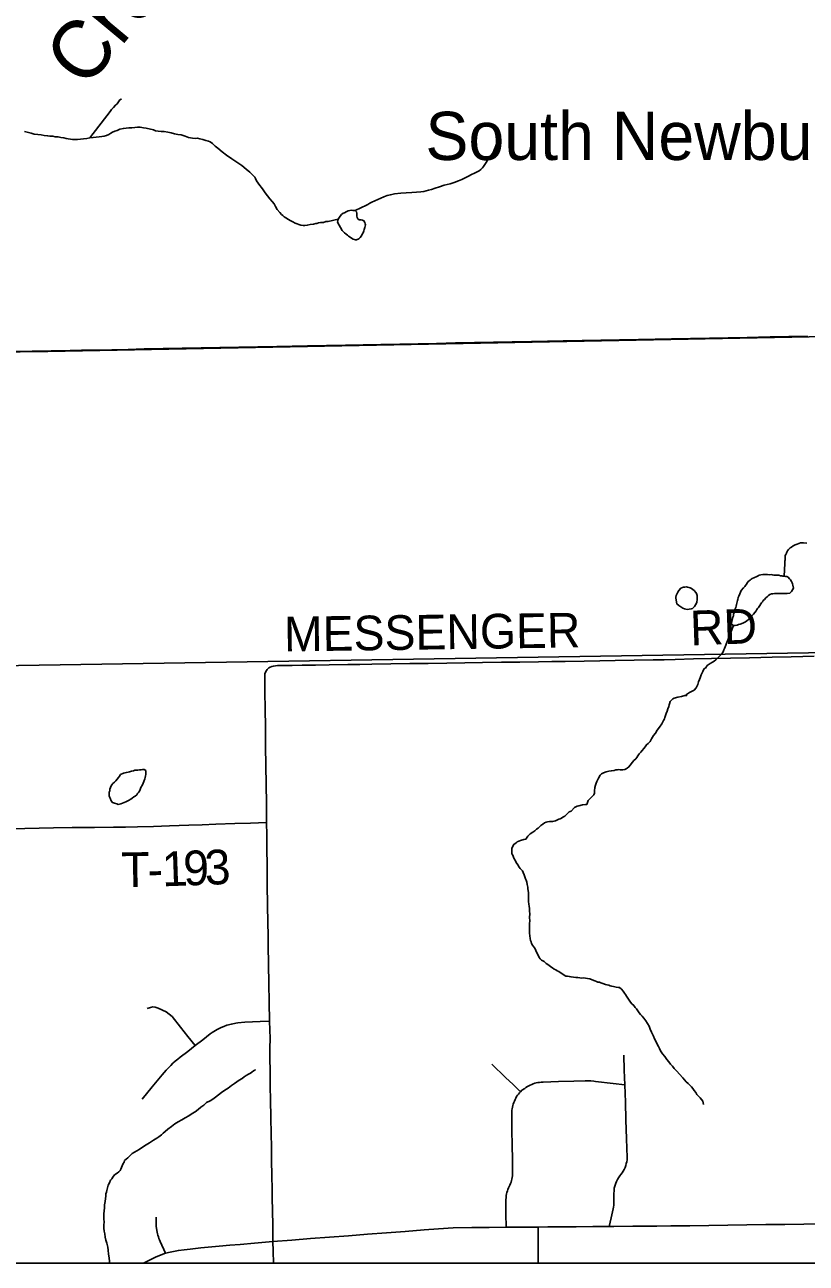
# Model space of a CAD drawing. Extents: x 103424 to 286016, y 38711 to 110967.
# Drawn here: x 136194 to 142995, y 38711 to 49490 of the extents above; entities that cross this region are included whole.
import ezdxf

# ---------------------------------------------------------------- set-up
doc = ezdxf.new("R2010")
doc.units = 0
for name, color, linetype in [('GM_X_Corporation', 7, 'Continuous'), ('GM_X_County_Road', 7, 'Continuous'), ('GM_X_County_Road_Text', 7, 'Continuous'), ('GM_X_Minor_Lake', 7, 'Continuous'), ('GM_X_Minor_River', 7, 'Continuous'), ('GM_X_Minor_River_Text', 7, 'Continuous'), ('GM_X_Rail_Line', 7, 'Continuous'), ('GM_X_Township_Road', 7, 'Continuous'), ('GM_X_Township_Road_Text', 7, 'Continuous'), ('GM_X_Unincorporated_Text', 7, 'Continuous')]:
    doc.layers.add(name, color=color, linetype=linetype)

msp = doc.modelspace()

# ---------------------------------------------------------------- linework, layer by layer
at = {"layer": 'GM_X_Corporation'}
for points in [[(103424, 96535), (103424, 38711), (175680, 38711), (175680, 110967), (119699, 110967), (119717, 106543), (119720, 106323), (119721, 106006), (119710, 99446), (119706, 99064), (119664, 96690), (117026, 96688), (115542, 96665), (105082, 96575)], [(119964, 38711), (149533, 38711), (149528, 39851), (149476, 42605), (149451, 44181), (147524, 44123), (147512, 44122), (144100, 44042), (133605, 43873), (130307, 43800), (126994, 43728), (121865, 43580), (119934, 43543)]]:
    msp.add_lwpolyline(points, close=True, dxfattribs=at)
msp.add_lwpolyline([(149451, 44181), (147524, 44123), (147512, 44122), (144100, 44042), (133605, 43873), (130307, 43800), (126994, 43728), (121865, 43580), (119934, 43543), (119908, 46302), (119860, 51427), (119800, 57497), (119747, 63221), (119711, 67089)], dxfattribs=at)
at = {"layer": 'GM_X_County_Road'}
for points in [[(136094, 46645), (136259, 46648), (136424, 46651), (136589, 46655), (136688, 46657), (136788, 46659), (136953, 46662), (137093, 46665), (137233, 46669), (137398, 46672), (137563, 46675), (137728, 46678), (137893, 46681), (138058, 46684), (138223, 46687), (138388, 46691), (138521, 46693), (138655, 46696), (138820, 46699), (138985, 46702), (139139, 46705), (139294, 46708), (139459, 46711), (139618, 46714), (139777, 46717), (139942, 46721), (140107, 46724), (140272, 46727), (140437, 46730), (140603, 46733), (140742, 46736), (140881, 46738), (141046, 46742), (141208, 46745), (141370, 46748), (141535, 46751), (141679, 46754), (141822, 46756), (141987, 46760), (142152, 46763), (142317, 46766), (142482, 46769), (142581, 46771), (142680, 46773), (142845, 46776), (143010, 46778)], [(138358, 38711), (138355, 38817), (138353, 38901), (138352, 39046), (138350, 39165), (138348, 39283), (138347, 39371), (138345, 39458), (138342, 39623), (138340, 39728), (138339, 39833), (138336, 39981), (138333, 40129), (138331, 40253), (138329, 40376), (138326, 40501), (138328, 40584), (138329, 40668), (138323, 40817), (138320, 40982), (138318, 41147), (138315, 41312), (138312, 41477), (138311, 41573), (138309, 41668), (138307, 41834), (138305, 41999), (138304, 42164), (138302, 42329), (138300, 42438), (138299, 42547), (138297, 42712), (138295, 42877), (138292, 43042), (138290, 43207), (138288, 43373), (138286, 43538), (138284, 43678), (138282, 43819), (138284, 43841), (138292, 43861), (138305, 43878), (138318, 43892), (138330, 43899), (138343, 43904), (138358, 43908), (138376, 43911), (138395, 43912), (138434, 43913), (138521, 43914), (138608, 43915), (138725, 43917), (138842, 43918), (139007, 43921), (139111, 43923), (139215, 43925), (139380, 43928), (139545, 43930), (139706, 43932), (139867, 43935), (140023, 43937), (140178, 43939), (140343, 43941), (140503, 43943), (140664, 43946), (140781, 43947), (140898, 43949), (141063, 43952), (141198, 43954), (141333, 43956), (141498, 43959), (141663, 43962), (141759, 43964), (141855, 43966), (142014, 43970), (142172, 43974), (142336, 43978), (142500, 43981), (142600, 43983), (142700, 43985), (142865, 43990), (142965, 43992), (143065, 43995)]]:
    msp.add_lwpolyline(points, dxfattribs=at)
at = {"layer": 'GM_X_Minor_Lake'}
for points in [[(139050, 47874), (139036, 47875), (139024, 47874), (139010, 47870), (138992, 47862), (138978, 47853), (138966, 47849), (138952, 47838), (138940, 47824), (138932, 47814), (138922, 47799), (138919, 47783), (138915, 47771)], [(138915, 47771), (138957, 47699), (138967, 47689), (138977, 47680), (138992, 47668), (139002, 47658), (139012, 47650), (139025, 47642), (139039, 47632), (139053, 47625), (139072, 47619), (139082, 47619), (139100, 47628), (139112, 47638), (139125, 47653), (139131, 47667), (139139, 47679), (139145, 47697), (139149, 47708), (139154, 47726), (139158, 47738), (139160, 47748), (139158, 47758), (139153, 47770), (139145, 47784), (139133, 47790), (139122, 47792), (139104, 47791), (139092, 47801), (139086, 47813), (139085, 47825), (139085, 47837), (139085, 47849), (139081, 47861), (139070, 47873), (139050, 47874)], [(142827, 44687), (142815, 44688), (142803, 44692), (142792, 44692), (142782, 44694), (142772, 44695), (142756, 44699), (142744, 44699), (142730, 44701), (142713, 44700), (142701, 44702), (142691, 44704), (142675, 44703), (142657, 44705), (142645, 44705), (142630, 44704), (142618, 44704), (142600, 44702), (142586, 44699), (142576, 44695), (142564, 44689), (142540, 44676), (142526, 44670), (142516, 44666), (142506, 44655), (142494, 44647), (142484, 44635), (142475, 44622), (142467, 44610), (142461, 44600), (142449, 44589), (142429, 44565), (142416, 44538), (142408, 44518), (142404, 44506), (142399, 44489), (142397, 44479), (142391, 44455), (142389, 44445), (142386, 44431), (142382, 44418), (142376, 44406), (142370, 44390), (142367, 44374), (142363, 44359), (142361, 44347), (142355, 44335), (142348, 44301), (142345, 44272)], [(142345, 44272), (142348, 44301), (142355, 44335), (142361, 44347), (142363, 44359), (142367, 44374), (142370, 44390), (142376, 44406), (142382, 44418), (142386, 44431), (142389, 44445), (142391, 44455), (142397, 44479), (142399, 44489), (142404, 44506), (142408, 44518), (142416, 44538), (142429, 44565), (142449, 44589), (142461, 44600), (142467, 44610), (142475, 44622), (142484, 44635), (142494, 44647), (142506, 44655), (142516, 44666), (142526, 44670), (142540, 44676), (142564, 44689), (142576, 44695), (142586, 44699), (142600, 44702), (142618, 44704), (142630, 44704), (142645, 44705), (142657, 44705), (142675, 44703), (142691, 44704), (142701, 44702), (142713, 44700), (142730, 44701), (142744, 44699), (142756, 44699), (142772, 44695), (142782, 44694), (142792, 44692), (142803, 44692), (142815, 44688), (142827, 44687), (142837, 44681), (142850, 44669), (142858, 44659), (142868, 44643), (142873, 44633), (142877, 44623), (142879, 44613), (142884, 44587), (142868, 44558), (142852, 44544), (142828, 44539), (142814, 44539), (142802, 44541), (142792, 44540), (142780, 44540), (142769, 44540), (142759, 44540), (142745, 44539), (142733, 44539), (142719, 44539), (142703, 44536), (142693, 44536), (142679, 44532), (142667, 44524), (142657, 44513), (142645, 44501), (142633, 44489), (142621, 44478), (142615, 44468), (142605, 44460), (142600, 44449), (142590, 44435), (142580, 44419), (142570, 44410), (142564, 44400), (142558, 44388), (142549, 44376), (142535, 44361), (142521, 44345), (142507, 44326), (142477, 44303), (142467, 44293), (142443, 44283), (142419, 44272), (142405, 44270), (142393, 44265), (142375, 44261), (142361, 44261), (142345, 44272)], [(142345, 44272), (142361, 44261), (142375, 44261), (142393, 44265), (142405, 44270), (142419, 44272), (142443, 44283), (142467, 44293), (142477, 44303), (142507, 44326), (142521, 44345), (142535, 44361), (142549, 44376), (142558, 44388), (142564, 44400), (142570, 44410), (142580, 44419), (142590, 44435), (142600, 44449), (142605, 44460), (142615, 44468), (142621, 44478), (142633, 44489), (142645, 44501), (142657, 44513), (142667, 44524), (142679, 44532), (142693, 44536), (142703, 44536), (142719, 44539), (142733, 44539), (142745, 44539), (142759, 44540), (142769, 44540), (142780, 44540), (142792, 44540), (142802, 44541), (142814, 44539), (142828, 44539), (142852, 44544), (142868, 44558), (142884, 44587), (142879, 44613), (142877, 44623), (142873, 44633), (142868, 44643), (142858, 44659), (142850, 44669), (142837, 44681), (142827, 44687)], [(142034, 44550), (142019, 44566), (142009, 44576), (141996, 44584), (141984, 44589), (141974, 44593), (141962, 44595), (141952, 44597), (141940, 44595), (141927, 44594), (141917, 44592), (141905, 44586), (141886, 44565), (141878, 44553), (141868, 44534), (141864, 44524), (141861, 44508), (141859, 44502), (141859, 44500)], [(141859, 44500), (141870, 44450), (141886, 44436), (141905, 44424), (141921, 44412), (141936, 44407), (141948, 44403), (141958, 44401), (141994, 44406), (142004, 44410), (142014, 44417), (142022, 44427), (142032, 44441), (142042, 44462), (142045, 44490), (142046, 44512), (142046, 44524), (142040, 44540), (142034, 44550), (142019, 44566), (142009, 44576), (141996, 44584), (141984, 44589), (141974, 44593), (141962, 44595), (141952, 44597), (141940, 44595), (141927, 44594), (141917, 44592), (141905, 44586), (141886, 44565), (141878, 44553), (141868, 44534), (141864, 44524), (141861, 44508), (141859, 44502), (141859, 44500)], [(141859, 44500), (141870, 44450), (141886, 44436), (141905, 44424), (141921, 44412), (141936, 44407), (141948, 44403), (141958, 44401), (141994, 44406), (142004, 44410), (142014, 44417), (142022, 44427), (142032, 44441), (142042, 44462), (142045, 44490), (142046, 44512), (142046, 44524), (142040, 44540), (142034, 44550)], [(137027, 42964), (137019, 42951), (137009, 42939), (136997, 42925), (136986, 42910), (136974, 42898), (136960, 42885), (136952, 42875), (136946, 42865), (136940, 42851), (136935, 42836), (136933, 42824), (136929, 42810), (136929, 42798), (136930, 42780), (136932, 42770), (136936, 42758), (136947, 42736), (136957, 42722), (136974, 42714), (136996, 42708), (137008, 42705), (137030, 42709), (137044, 42716), (137060, 42722), (137074, 42726), (137086, 42733), (137098, 42737), (137118, 42749), (137130, 42760), (137142, 42770), (137156, 42777), (137170, 42789), (137176, 42799), (137184, 42809), (137192, 42820), (137197, 42834), (137205, 42852), (137219, 42875), (137225, 42889), (137230, 42905), (137238, 42926), (137242, 42938), (137245, 42954), (137247, 42964), (137249, 42974), (137249, 42987), (137248, 42999), (137234, 43008), (137220, 43008), (137206, 43006), (137192, 43005), (137178, 43003), (137166, 43003), (137151, 43001), (137139, 42998), (137123, 42994), (137107, 42989), (137093, 42985), (137079, 42983), (137065, 42978), (137053, 42976), (137027, 42964)], [(137156, 42777), (137170, 42789), (137176, 42799), (137184, 42809), (137192, 42820), (137197, 42834), (137205, 42852), (137219, 42875), (137225, 42889), (137230, 42905), (137238, 42926), (137242, 42938), (137245, 42954), (137247, 42964), (137249, 42974), (137249, 42987), (137248, 42999), (137234, 43008), (137220, 43008), (137206, 43006), (137192, 43005), (137178, 43003), (137166, 43003), (137151, 43001), (137139, 42998), (137123, 42994), (137107, 42989), (137093, 42985), (137079, 42983), (137065, 42978), (137053, 42976), (137027, 42964)], [(137027, 42964), (137019, 42951), (137009, 42939), (136997, 42925), (136986, 42910), (136974, 42898), (136960, 42885), (136952, 42875), (136946, 42865), (136940, 42851), (136935, 42836), (136933, 42824), (136929, 42810), (136929, 42798), (136930, 42780), (136932, 42770), (136936, 42758), (136947, 42736), (136957, 42722), (136974, 42714), (136996, 42708), (137008, 42705), (137030, 42709), (137044, 42716), (137060, 42722), (137074, 42726), (137086, 42733), (137098, 42737), (137118, 42749), (137130, 42760), (137142, 42770), (137156, 42777)]]:
    msp.add_lwpolyline(points, dxfattribs=at)
at = {"layer": 'GM_X_Minor_River'}
for points in [[(136759, 48505), (136936, 48735), (136949, 48752), (136965, 48770), (136983, 48789), (136999, 48803), (137009, 48818), (137022, 48836), (137032, 48842), (137034, 48843), (137036, 48845)], [(136192, 48560), (136226, 48552), (136251, 48545), (136277, 48539), (136307, 48536), (136336, 48533), (136364, 48527), (136392, 48524), (136415, 48520), (136437, 48519), (136459, 48515)], [(136459, 48515), (136486, 48514), (136508, 48508), (136534, 48505), (136555, 48501), (136573, 48497), (136593, 48494), (136611, 48490), (136632, 48491), (136654, 48491), (136678, 48494), (136704, 48498), (136735, 48501), (136759, 48505), (136789, 48510), (136815, 48513), (136843, 48515), (136866, 48518), (136884, 48520), (136904, 48527), (136926, 48535), (136942, 48546), (136958, 48556), (136978, 48565), (136998, 48571), (137020, 48580), (137052, 48587), (137076, 48591), (137100, 48592), (137125, 48594), (137151, 48597), (137175, 48599), (137199, 48598), (137226, 48594), (137250, 48591), (137315, 48576), (137333, 48568), (137356, 48563), (137382, 48561), (137408, 48560), (137439, 48555), (137469, 48549), (137498, 48542), (137526, 48536), (137556, 48531), (137589, 48521), (137620, 48508), (137654, 48503), (137676, 48501), (137697, 48502), (137719, 48498), (137743, 48491), (137770, 48483), (137792, 48477), (137808, 48470), (137827, 48456), (137850, 48434), (137874, 48415), (137913, 48383), (137950, 48356), (137995, 48324), (138041, 48295), (138082, 48266), (138121, 48234), (138152, 48207), (138174, 48187), (138189, 48173), (138195, 48163), (138201, 48151), (138210, 48131), (138226, 48111), (138239, 48091), (138253, 48074), (138268, 48052), (138287, 48028), (138308, 48000), (138328, 47974), (138347, 47951), (138364, 47931), (138376, 47909), (138391, 47883), (138414, 47855), (138428, 47839), (138441, 47829), (138453, 47818), (138504, 47786), (138527, 47775), (138547, 47763), (138565, 47757), (138578, 47752), (138596, 47746), (138618, 47742), (138632, 47743), (138653, 47745), (138679, 47752), (138707, 47754), (138727, 47759), (138737, 47761), (138751, 47765), (138769, 47768), (138781, 47770)], [(139070, 47873), (139168, 47920), (139180, 47926), (139196, 47937), (139216, 47947), (139240, 47958), (139266, 47970), (139294, 47981), (139320, 47992), (139348, 48003), (139376, 48011), (139411, 48018), (139467, 48025), (139514, 48028), (139562, 48031), (139604, 48034), (139641, 48037), (139667, 48040), (139687, 48044), (139709, 48051), (139735, 48057), (139767, 48068), (139804, 48079), (139844, 48094), (139896, 48105), (139932, 48118), (139968, 48131), (139998, 48144), (140028, 48159), (140056, 48173), (140082, 48186), (140108, 48199), (140132, 48209), (140150, 48220), (140164, 48230), (140178, 48245), (140186, 48257), (140197, 48273), (140209, 48292), (140221, 48310), (140233, 48329), (140245, 48343), (140254, 48355), (140264, 48370), (140272, 48384), (140280, 48400), (140287, 48423), (140297, 48445), (140306, 48470), (140316, 48494), (140324, 48508), (140332, 48527), (140334, 48529), (140333, 48531)], [(138781, 47770), (138794, 47770), (138814, 47777), (138824, 47777), (138836, 47779), (138922, 47799)], [(142803, 44692), (142811, 44856), (142812, 44830), (142811, 44856), (142813, 44870), (142817, 44880), (142823, 44890), (142826, 44901), (142832, 44911), (142842, 44923), (142856, 44936), (142868, 44944), (142880, 44954), (142898, 44965), (142916, 44969), (142944, 44980), (142970, 44980), (143001, 44979)], [(141277, 42993), (141299, 42998), (141323, 43000), (141339, 43005), (141351, 43005), (141361, 43007), (141375, 43006), (141398, 43006), (141416, 43008), (141428, 43015), (141438, 43021), (141452, 43031), (141495, 43087), (141511, 43101), (141521, 43114), (141530, 43128), (141542, 43144), (141556, 43159), (141568, 43173), (141582, 43190), (141593, 43206), (141605, 43223), (141619, 43235), (141637, 43253), (141648, 43276), (141666, 43303), (141684, 43325), (141699, 43350), (141719, 43376), (141739, 43407), (141752, 43434), (141762, 43450), (141766, 43460), (141771, 43478), (141777, 43495), (141785, 43515), (141792, 43537), (141798, 43556), (141802, 43570), (141804, 43580), (141811, 43600), (141833, 43623), (141845, 43629), (141877, 43638), (141911, 43645), (141940, 43652), (141954, 43652), (141953, 43662), (141979, 43677), (142003, 43689), (142019, 43698), (142037, 43720), (142051, 43747), (142058, 43771), (142066, 43792), (142072, 43806), (142081, 43832), (142095, 43861), (142108, 43886), (142118, 43890), (142134, 43912), (142160, 43931), (142180, 43942), (142194, 43952), (142208, 43964), (142224, 43977), (142261, 44016), (142271, 44032), (142279, 44049), (142285, 44061), (142361, 44261)], [(140639, 41441), (140630, 41457), (140622, 41469), (140614, 41479), (140605, 41495), (140601, 41507), (140595, 41519), (140592, 41537), (140590, 41561), (140587, 41585), (140587, 41609), (140586, 41640), (140587, 41668), (140589, 41692), (140588, 41720), (140590, 41753), (140587, 41775), (140587, 41799), (140584, 41819), (140582, 41837), (140579, 41860), (140579, 41884), (140578, 41908), (140578, 41934), (140575, 41956), (140573, 41970), (140571, 41985), (140566, 42007), (140564, 42029), (140557, 42045), (140553, 42057), (140546, 42073), (140540, 42091), (140533, 42111), (140525, 42125), (140517, 42135), (140506, 42147), (140496, 42159), (140486, 42179), (140471, 42198), (140462, 42218), (140454, 42232), (140448, 42244), (140444, 42254), (140441, 42264), (140433, 42274), (140434, 42325), (140451, 42356), (140471, 42370), (140479, 42380), (140509, 42391), (140537, 42400), (140556, 42402), (140571, 42429), (140593, 42447), (140617, 42462), (140633, 42475), (140647, 42489), (140661, 42499), (140675, 42510), (140686, 42522), (140702, 42533), (140718, 42545), (140732, 42549), (140742, 42552), (140762, 42556), (140775, 42556), (140791, 42557), (140801, 42559), (140813, 42561), (140825, 42568), (140841, 42576), (140855, 42580), (140865, 42585), (140877, 42593), (140895, 42603), (140913, 42620), (140932, 42639), (140949, 42645), (140978, 42678), (141002, 42689), (141016, 42691), (141048, 42702), (141073, 42704), (141085, 42704), (141098, 42737), (141126, 42768), (141148, 42787), (141153, 42801), (141153, 42823), (141156, 42851), (141162, 42872), (141166, 42888), (141173, 42904), (141179, 42914), (141187, 42933), (141203, 42959), (141212, 42970), (141230, 42978), (141254, 42987), (141277, 42993)], [(142102, 40094), (142094, 40122), (142073, 40152), (142054, 40167), (142044, 40181), (142034, 40197), (142021, 40215), (142009, 40231), (141996, 40247), (141982, 40261), (141967, 40275), (141951, 40290), (141936, 40308), (141920, 40324), (141866, 40385), (141847, 40405), (141831, 40425), (141814, 40445), (141799, 40465), (141783, 40483), (141766, 40510), (141745, 40534), (141733, 40552), (141725, 40566), (141718, 40580), (141710, 40596), (141699, 40618), (141686, 40644), (141674, 40664), (141665, 40686), (141657, 40704), (141648, 40722), (141638, 40748), (141627, 40774), (141614, 40798), (141598, 40822), (141581, 40844), (141567, 40861), (141552, 40877), (141542, 40891), (141531, 40909), (141519, 40925), (141506, 40937), (141494, 40953), (141477, 40969), (141465, 40982), (141455, 41000), (141442, 41018), (141432, 41036), (141421, 41050), (141413, 41062), (141402, 41080), (141388, 41096), (141371, 41110), (141361, 41111), (141341, 41115), (141329, 41117), (141319, 41119), (141302, 41122), (141288, 41126), (141276, 41132), (141260, 41135), (141247, 41137), (141225, 41147), (141207, 41152), (141195, 41156), (141182, 41158), (141170, 41164), (141154, 41169), (141133, 41179), (141111, 41187), (141091, 41190), (141073, 41192), (141058, 41194), (141040, 41193), (141026, 41195), (141008, 41197), (140990, 41198), (140969, 41202), (140949, 41203), (140933, 41207), (140917, 41209), (140902, 41210), (140888, 41218), (140876, 41228), (140855, 41242), (140841, 41249), (140827, 41257), (140816, 41265), (140802, 41271), (140788, 41283), (140773, 41292), (140755, 41306), (140732, 41320), (140714, 41338), (140691, 41349), (140681, 41359), (140671, 41371), (140654, 41411), (140645, 41425), (140639, 41441)], [(136934, 38711), (136931, 38726), (136929, 38758), (136924, 38790), (136921, 38824), (136917, 38852), (136908, 38887), (136899, 38911), (136894, 38939), (136892, 38967), (136885, 38991), (136883, 39015), (136882, 39043), (136884, 39072), (136883, 39096), (136883, 39116), (136882, 39140), (136884, 39167), (136887, 39193), (136889, 39219), (136894, 39248), (136897, 39274), (136899, 39294), (136901, 39314), (136904, 39331), (136908, 39345), (136914, 39367), (136921, 39390), (136931, 39410), (136941, 39434), (136952, 39447), (136960, 39459), (136974, 39480), (136998, 39496), (137014, 39507), (137024, 39519), (137031, 39531), (137035, 39543), (137041, 39560), (137049, 39580), (137060, 39592), (137062, 39605), (137090, 39629), (137128, 39667), (137190, 39700), (137235, 39732), (137279, 39759), (137315, 39782), (137343, 39801), (137361, 39811), (137373, 39821), (137385, 39830), (137399, 39842), (137417, 39859), (137438, 39877), (137472, 39902), (137500, 39923), (137530, 39942), (137560, 39959), (137590, 39977), (137622, 39994), (137650, 40013), (137678, 40030), (137704, 40049), (137727, 40069), (137753, 40088), (137777, 40109), (137809, 40124), (137831, 40138), (137855, 40157), (137879, 40176), (137907, 40196), (137934, 40217), (137964, 40236), (137992, 40257), (138018, 40274), (138040, 40290), (138060, 40305), (138086, 40319), (138104, 40332), (138122, 40344), (138140, 40357)], [(138140, 40357), (138158, 40365), (138170, 40374), (138185, 40386), (138195, 40392), (138199, 40393), (138201, 40395)]]:
    msp.add_lwpolyline(points, dxfattribs=at)
at = {"layer": 'GM_X_Rail_Line'}
msp.add_lwpolyline([(103424, 43098), (108679, 43247), (116958, 43465), (121815, 43564), (126930, 43718), (126994, 43782), (126945, 46442), (126989, 46497), (133018, 46607), (136395, 46646), (144376, 46799), (146505, 45438), (151249, 45326)], dxfattribs=at)
at = {"layer": 'GM_X_Township_Road'}
for points in [[(136029, 42491), (136194, 42495), (136319, 42497), (136443, 42500), (136608, 42502), (136705, 42502), (136802, 42503), (136967, 42506), (137071, 42507), (137176, 42509), (137315, 42513), (137455, 42518), (137538, 42521), (137621, 42524), (137739, 42528), (137857, 42532), (138022, 42538), (138160, 42542), (138299, 42547)], [(137258, 40928), (137289, 40938), (137309, 40942), (137330, 40940), (137356, 40931), (137425, 40898), (137477, 40858), (137548, 40765), (137613, 40685), (137678, 40606)], [(137215, 40140), (137302, 40245), (137389, 40351), (137407, 40372), (137425, 40392), (137444, 40412), (137464, 40432), (137484, 40451), (137504, 40469), (137526, 40487), (137547, 40504), (137613, 40555), (137678, 40606), (137743, 40656), (137809, 40707), (137824, 40718), (137869, 40745), (137904, 40762), (137927, 40772), (137954, 40782), (137992, 40792), (138030, 40800), (138048, 40803), (138108, 40809), (138244, 40814), (138323, 40817)], [(140260, 40443), (140379, 40329), (140444, 40266), (140508, 40204)], [(141280, 39031), (141297, 39105), (141314, 39184), (141318, 39200), (141320, 39217), (141322, 39234), (141321, 39312), (141323, 39347), (141325, 39365), (141329, 39382), (141337, 39407), (141344, 39423), (141352, 39439), (141361, 39454), (141374, 39472), (141383, 39483), (141394, 39498), (141403, 39513), (141411, 39528), (141418, 39544), (141424, 39561), (141429, 39578), (141433, 39595), (141436, 39612), (141437, 39630), (141431, 39795), (141426, 39960), (141421, 40112), (141416, 40264), (141412, 40392), (141407, 40521)], [(140383, 39025), (140382, 39142), (140381, 39260), (140383, 39287), (140384, 39301), (140387, 39315), (140390, 39328), (140394, 39341), (140399, 39354), (140404, 39367), (140410, 39379), (140416, 39392), (140422, 39404), (140426, 39417), (140431, 39431), (140434, 39444), (140436, 39458), (140438, 39471), (140439, 39485), (140438, 39593), (140435, 39758), (140434, 39846), (140433, 39935), (140434, 40042), (140436, 40056), (140438, 40070), (140441, 40083), (140445, 40097), (140449, 40110), (140455, 40123), (140461, 40136), (140467, 40149), (140474, 40161), (140482, 40173), (140490, 40184), (140499, 40195), (140508, 40204), (140521, 40216), (140545, 40232), (140556, 40241), (140568, 40248), (140580, 40255), (140593, 40261), (140606, 40267), (140619, 40272), (140632, 40277), (140646, 40280), (140660, 40283), (140673, 40285), (140687, 40287), (140705, 40288), (140839, 40292), (140973, 40296), (141070, 40299), (141121, 40298), (141146, 40296), (141161, 40294), (141314, 40276), (141416, 40264)], [(137223, 38711), (137228, 38713), (137333, 38763), (137396, 38790), (137418, 38798), (137460, 38808), (137532, 38822), (137582, 38829), (137634, 38835), (137725, 38845), (137887, 38860), (137979, 38867), (138070, 38874), (138193, 38886), (138353, 38901), (138518, 38913), (138682, 38926), (138847, 38938), (139012, 38951), (139176, 38963), (139341, 38976), (139505, 38988), (139670, 39001), (139795, 39010), (139921, 39020), (140086, 39022), (140235, 39023), (140383, 39025), (140523, 39025), (140663, 39026), (140746, 39027), (140829, 39027), (140994, 39029), (141137, 39030), (141280, 39031), (141321, 39031), (141486, 39033), (141590, 39034), (141695, 39035), (141818, 39036), (141983, 39038), (142148, 39040), (142313, 39042), (142478, 39044), (142643, 39047), (142809, 39049), (142974, 39051), (143139, 39053)], [(137418, 38798), (137372, 38901), (137367, 38914), (137362, 38927), (137357, 38940), (137353, 38954), (137349, 38967), (137346, 38981), (137344, 38995), (137341, 39016), (137339, 39030), (137338, 39044), (137338, 39058), (137339, 39111)], [(140662, 38711), (140662, 38761), (140661, 38872), (140663, 39026)]]:
    msp.add_lwpolyline(points, dxfattribs=at)

# ---------------------------------------------------------------- texts
at = {"layer": 'GM_X_County_Road_Text'}
for s, rotation, p in [('MESSENGER', 0.8066, (138452, 44035)), ('RD', 1.9711, (141989, 44088))]:
    msp.add_text(s, height=301.9, rotation=rotation, dxfattribs=at).set_placement(p)
at = {"layer": 'GM_X_Minor_River_Text'}
msp.add_text('Creek', height=503.4, rotation=50.2016, dxfattribs=at).set_placement((136720, 48921))
at = {"layer": 'GM_X_Township_Road_Text'}
for s, rotation, p in [('T', 0.5614, (137034, 41985)), ('1', 1.9688, (137392, 41991)), ('9', 2.1855, (137579, 41997)), ('3', 2.2253, (137765, 42004)), ('-', 1.6656, (137267, 41987))]:
    msp.add_text(s, height=302, rotation=rotation, dxfattribs=at).set_placement(p)
at = {"layer": 'GM_X_Unincorporated_Text'}
msp.add_text('South Newbury', height=419.6, rotation=0, dxfattribs=at).set_placement((139681, 48313))

doc.saveas('drawing.dxf')
